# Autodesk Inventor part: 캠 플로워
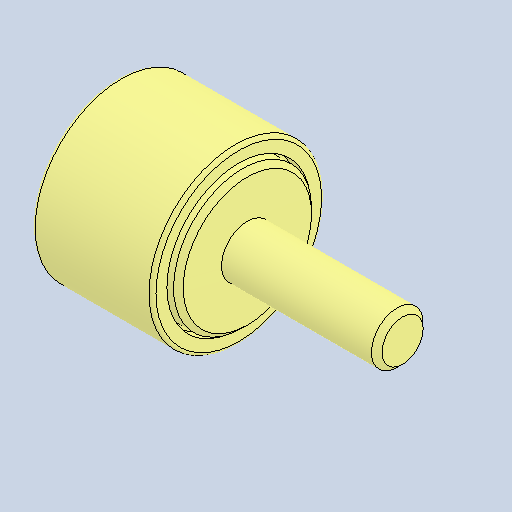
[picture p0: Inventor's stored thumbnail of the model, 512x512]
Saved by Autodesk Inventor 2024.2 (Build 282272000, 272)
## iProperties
Created: 2025-09
Part Number: 캠 플로워
Material: 일반
Description: Cam Follower with a Hexagon Socket Model CF-A-
Document SubType Name: Modeling
Designer: home
Density: 1 g/cm^3
Appearance: 기본값
Company: THK
Author: jhkim
Sending System: Autodesk Inventor 2026
Preprocessor: ST-DEVELOPER v20.1
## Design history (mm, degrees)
feature "Solid1"
node "솔리드1"
